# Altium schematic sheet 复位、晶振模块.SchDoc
size A4; Address1: 张三; Address2: 202311001; Address3: 23应用电子1班
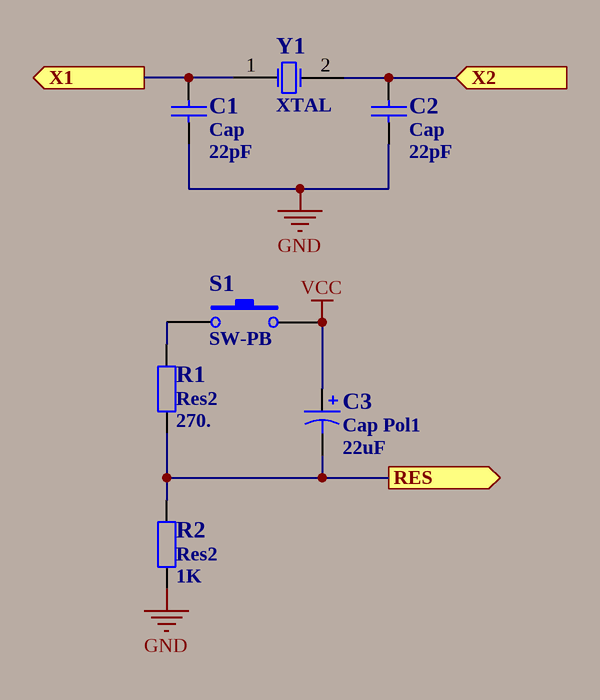
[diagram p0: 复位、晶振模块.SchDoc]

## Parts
C1  Cap  value 22pF  [RAD-0.1]
C2  Cap  value 22pF  [RAD-0.1]
C3  Cap Pol1  value 22uF  [电解电容-100uF]
R1  Res2  value 270.  [AXIAL-0.4]
R2  Res2  value 1K  [AXIAL-0.4]
S1  SW-PB  [轻触开关]
Y1  XTAL  [SPST-2]

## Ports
RES (out), X1 (out), X2 (in)

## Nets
GND: C1.2 C2.2 R2.1
VCC: C3.1 S1.2
RES: C3.2 R1.1 R2.2 ; port RES
X1: C1.1 Y1.1(OSC1) ; port X1
X2: C2.1 Y1.2(OSC2) ; port X2
NetR1_2: R1.2 S1.1

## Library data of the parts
C1 C2 = Cap: Capacitor
C3 = Cap Pol1: Polarized Capacitor (Radial)
R1 R2 = Res2: Resistor
S1 = SW-PB: Switch
Y1 = XTAL: Crystal Oscillator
